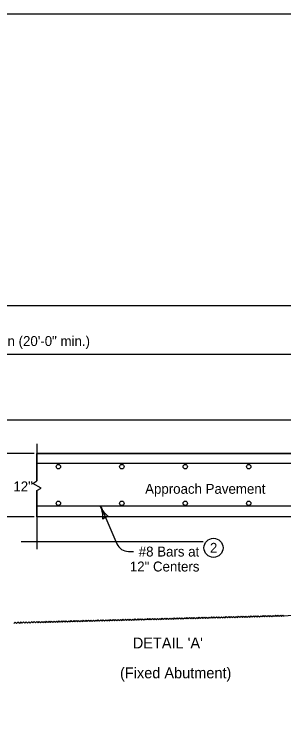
# Model space of a CAD drawing. Extents: x -2135039 to -2124495, y -2139046 to -2132546.
# Drawn here: x -2133798 to -2133364, y -2133685 to -2132546 of the extents above; entities that cross this region are included whole.
import ezdxf

# ---------------------------------------------------------------- set-up
doc = ezdxf.new("R2010")
doc.units = 0
for name, color, linetype in [('BridgeSuperStructureExisting', 7, 'Continuous'), ('dsnAlignmentStation', 7, 'Continuous'), ('dsnCellElements', 7, 'Continuous'), ('dsnStdLabel', 7, 'Continuous'), ('dsnStdLineWork', 7, 'Continuous')]:
    doc.layers.add(name, color=color, linetype=linetype)

msp = doc.modelspace()

# ---------------------------------------------------------------- linework, layer by layer
at = {"layer": 'BridgeSuperStructureExisting'}
for p, q in [((-2133761.6, -2133238.6), (-2133761.6, -2133298.7)), ((-2133142.6, -2133254.3), (-2133761.6, -2133254.3)), ((-2133761.6, -2133298.7), (-2133761.6, -2133254.3)), ((-2133761.6, -2133254.3), (-2133142.6, -2133254.3)), ((-2133157.7, -2133270.6), (-2133761.6, -2133270.6)), ((-2133761.6, -2133298.7), (-2133761.6, -2133298.7)), ((-2133761.6, -2133313.9), (-2133761.6, -2133408.5)), ((-2133761.6, -2133356.6), (-2133761.6, -2133313.9)), ((-2133157.7, -2133339.5), (-2133761.6, -2133339.5)), ((-2133142.6, -2133356.6), (-2133761.6, -2133356.6))]:
    msp.add_line(p, q, dxfattribs=at)
msp.add_lwpolyline([(-2133761.6, -2133313.9), (-2133755, -2133310.1), (-2133768.2, -2133302.5), (-2133761.6, -2133298.7)], dxfattribs=at)
msp.add_lwpolyline([(-2133761.6, -2133313.9), (-2133755, -2133310.1), (-2133768.2, -2133302.5), (-2133761.6, -2133298.7)], dxfattribs=at)
for centre, radius in [((-2133727.1, -2133275.6), 3.55), ((-2133624.8, -2133275.6), 3.55), ((-2133522.5, -2133275.6), 3.55), ((-2133420.2, -2133275.6), 3.55), ((-2133727.1, -2133334.6), 3.55), ((-2133624.8, -2133334.6), 3.55), ((-2133522.5, -2133334.6), 3.55), ((-2133420.2, -2133334.6), 3.55), ((-2133477, -2133406.4), 15.4)]:
    msp.add_circle(centre, radius, dxfattribs=at)
at = {"layer": 'dsnAlignmentStation'}
msp.add_lwpolyline([(-2134934.4, -2133016), (-2131799.4, -2133016), (-2131799.4, -2135026), (-2134934.4, -2135026)], close=True, dxfattribs=at)
at = {"layer": 'dsnCellElements'}
for centre, radius, start, end in [((-2133620, -2133322.8), 42.5, 203.6401, 231.7126), ((-2133697.9, -2133356.9), 42.5, 355.5676, 23.6401), ((-2133644.6, -2133372.5), 16.4, 95.9068, 131.3735)]:
    msp.add_arc(centre, radius, start, end, dxfattribs=at)
at = {"layer": 'dsnStdLabel'}
for p, q in [((-2134514.3, -2133094.1), (-2133142.6, -2133094.1)), ((-2133215.6, -2133200.6), (-2133828, -2133200.6)), ((-2133766.1, -2133254.4), (-2133865.6, -2133254.4)), ((-2133658.9, -2133339.8), (-2133632.6, -2133400)), ((-2133766.1, -2133356.7), (-2133865.6, -2133356.7)), ((-2133142.6, -2133356.6), (-2133761.6, -2133356.6)), ((-2133787.2, -2133396), (-2133493.8, -2133396)), ((-2133614.1, -2133412.1), (-2133605.9, -2133412.1)), ((-2133760.8, -2133526.1), (-2132665.9, -2133497.5))]:
    msp.add_line(p, q, dxfattribs=at)
for points in [[(-2133760.8, -2133526.1), (-2133759.8, -2133527.1), (-2133757.9, -2133525.1), (-2133755.9, -2133527), (-2133753.9, -2133525), (-2133751.9, -2133526.9), (-2133750, -2133524.9), (-2133747.9, -2133526.8), (-2133746, -2133524.8), (-2133743.9, -2133526.7), (-2133742, -2133524.7), (-2133740, -2133526.6), (-2133738.1, -2133524.5), (-2133736, -2133526.5), (-2133734.1, -2133524.4), (-2133732, -2133526.4), (-2133730.1, -2133524.3), (-2133728.1, -2133526.3), (-2133726.1, -2133524.2), (-2133724.1, -2133526.2), (-2133722.2, -2133524.1), (-2133720.2, -2133526.1), (-2133718.2, -2133524), (-2133716.2, -2133526), (-2133714.3, -2133523.9), (-2133713.2, -2133524.9)], [(-2133713.2, -2133524.9), (-2133712.2, -2133525.9), (-2133710.3, -2133523.8), (-2133708.2, -2133525.8), (-2133706.3, -2133523.7), (-2133704.3, -2133525.7), (-2133702.3, -2133523.6), (-2133700.3, -2133525.5), (-2133698.4, -2133523.5), (-2133696.3, -2133525.4), (-2133694.4, -2133523.4), (-2133692.4, -2133525.3), (-2133690.4, -2133523.3), (-2133688.4, -2133525.2), (-2133686.5, -2133523.2), (-2133684.4, -2133525.1), (-2133682.5, -2133523.1), (-2133680.5, -2133525), (-2133678.5, -2133523), (-2133676.5, -2133524.9), (-2133674.6, -2133522.9), (-2133672.5, -2133524.8), (-2133670.6, -2133522.8), (-2133668.6, -2133524.7), (-2133666.6, -2133522.7), (-2133665.6, -2133523.6)], [(-2133665.6, -2133523.6), (-2133664.6, -2133524.6), (-2133662.7, -2133522.6), (-2133660.6, -2133524.5), (-2133658.7, -2133522.5), (-2133656.7, -2133524.4), (-2133654.7, -2133522.4), (-2133652.7, -2133524.3), (-2133650.8, -2133522.3), (-2133648.7, -2133524.2), (-2133646.8, -2133522.2), (-2133644.8, -2133524.1), (-2133642.8, -2133522.1), (-2133640.8, -2133524), (-2133638.9, -2133522), (-2133636.8, -2133523.9), (-2133634.9, -2133521.9), (-2133632.9, -2133523.8), (-2133630.9, -2133521.8), (-2133628.9, -2133523.7), (-2133627, -2133521.7), (-2133624.9, -2133523.6), (-2133623, -2133521.5), (-2133621, -2133523.5), (-2133619, -2133521.4), (-2133618, -2133522.4)], [(-2133618, -2133522.4), (-2133617, -2133523.4), (-2133615.1, -2133521.3), (-2133613, -2133523.3), (-2133611.1, -2133521.2), (-2133609.1, -2133523.2), (-2133607.1, -2133521.1), (-2133605.1, -2133523.1), (-2133603.2, -2133521), (-2133601.1, -2133523), (-2133599.2, -2133520.9), (-2133597.2, -2133522.9), (-2133595.2, -2133520.8), (-2133593.2, -2133522.8), (-2133591.3, -2133520.7), (-2133589.2, -2133522.6), (-2133587.3, -2133520.6), (-2133585.3, -2133522.5), (-2133583.3, -2133520.5), (-2133581.3, -2133522.4), (-2133579.4, -2133520.4), (-2133577.3, -2133522.3), (-2133575.4, -2133520.3), (-2133573.4, -2133522.2), (-2133571.4, -2133520.2), (-2133570.4, -2133521.2)], [(-2133570.4, -2133521.2), (-2133569.4, -2133522.1), (-2133567.5, -2133520.1), (-2133565.4, -2133522), (-2133563.5, -2133520), (-2133561.5, -2133521.9), (-2133559.5, -2133519.9), (-2133557.5, -2133521.8), (-2133555.6, -2133519.8), (-2133553.5, -2133521.7), (-2133551.6, -2133519.7), (-2133549.6, -2133521.6), (-2133547.6, -2133519.6), (-2133545.6, -2133521.5), (-2133543.7, -2133519.5), (-2133541.6, -2133521.4), (-2133539.7, -2133519.4), (-2133537.6, -2133521.3), (-2133535.7, -2133519.3), (-2133533.7, -2133521.2), (-2133531.8, -2133519.2), (-2133529.7, -2133521.1), (-2133527.8, -2133519.1), (-2133525.7, -2133521), (-2133523.8, -2133519), (-2133522.8, -2133519.9)], [(-2133522.8, -2133519.9), (-2133521.8, -2133520.9), (-2133519.8, -2133518.9), (-2133517.8, -2133520.8), (-2133515.9, -2133518.7), (-2133513.8, -2133520.7), (-2133511.9, -2133518.6), (-2133509.9, -2133520.6), (-2133507.9, -2133518.5), (-2133505.9, -2133520.5), (-2133504, -2133518.4), (-2133501.9, -2133520.4), (-2133500, -2133518.3), (-2133498, -2133520.3), (-2133496, -2133518.2), (-2133494, -2133520.2), (-2133492.1, -2133518.1), (-2133490, -2133520.1), (-2133488.1, -2133518), (-2133486.1, -2133520), (-2133484.1, -2133517.9), (-2133482.1, -2133519.8), (-2133480.2, -2133517.8), (-2133478.1, -2133519.7), (-2133476.2, -2133517.7), (-2133475.2, -2133518.7)], [(-2133475.2, -2133518.7), (-2133474.2, -2133519.6), (-2133472.2, -2133517.6), (-2133470.2, -2133519.5), (-2133468.3, -2133517.5), (-2133466.2, -2133519.4), (-2133464.3, -2133517.4), (-2133462.3, -2133519.3), (-2133460.3, -2133517.3), (-2133458.3, -2133519.2), (-2133456.4, -2133517.2), (-2133454.3, -2133519.1), (-2133452.4, -2133517.1), (-2133450.4, -2133519), (-2133448.4, -2133517), (-2133446.4, -2133518.9), (-2133444.5, -2133516.9), (-2133442.4, -2133518.8), (-2133440.5, -2133516.8), (-2133438.5, -2133518.7), (-2133436.5, -2133516.7), (-2133434.5, -2133518.6), (-2133432.6, -2133516.6), (-2133430.5, -2133518.5), (-2133428.6, -2133516.5), (-2133427.6, -2133517.4)], [(-2133427.6, -2133517.4), (-2133426.6, -2133518.4), (-2133424.6, -2133516.4), (-2133422.6, -2133518.3), (-2133420.7, -2133516.3), (-2133418.6, -2133518.2), (-2133416.7, -2133516.2), (-2133414.7, -2133518.1), (-2133412.7, -2133516.1), (-2133410.7, -2133518), (-2133408.8, -2133515.9), (-2133406.7, -2133517.9), (-2133404.8, -2133515.8), (-2133402.8, -2133517.8), (-2133400.8, -2133515.7), (-2133398.8, -2133517.7), (-2133396.9, -2133515.6), (-2133394.8, -2133517.6), (-2133392.9, -2133515.5), (-2133390.9, -2133517.5), (-2133388.9, -2133515.4), (-2133386.9, -2133517.4), (-2133385, -2133515.3), (-2133382.9, -2133517.3), (-2133381, -2133515.2), (-2133380, -2133516.2)], [(-2133380, -2133516.2), (-2133379, -2133517.2), (-2133377, -2133515.1), (-2133375, -2133517.1), (-2133373.1, -2133515), (-2133371, -2133516.9), (-2133369.1, -2133514.9), (-2133367.1, -2133516.8), (-2133365.1, -2133514.8), (-2133363.1, -2133516.7)], [(-2133760.6, -2133526.3), (-2133761.7, -2133525.2), (-2133763.9, -2133527.4), (-2133766.1, -2133525.3), (-2133768.2, -2133527.5), (-2133770.4, -2133525.4), (-2133772.6, -2133527.7), (-2133774.8, -2133525.5), (-2133776.9, -2133527.8), (-2133779.2, -2133525.7), (-2133781.3, -2133527.9), (-2133783.5, -2133525.8), (-2133785.6, -2133528), (-2133787.9, -2133525.9), (-2133790, -2133528.1), (-2133792.2, -2133526), (-2133794.4, -2133528.2), (-2133796.6, -2133526.1), (-2133798.7, -2133528.3)]]:
    msp.add_lwpolyline(points, dxfattribs=at)
msp.add_arc((-2133614.1, -2133391.9), 20.2, 203.6401, 270, dxfattribs=at)
at = {"layer": 'dsnStdLineWork'}
msp.add_lwpolyline([(-2135038.9, -2135130.5), (-2131694.9, -2135130.5), (-2131694.9, -2132546.5), (-2135038.9, -2132546.5)], close=True, dxfattribs=at)

# ---------------------------------------------------------------- texts
at = {"layer": 'BridgeSuperStructureExisting'}
msp.add_text("DETAIL 'A' ", height=17.5, dxfattribs=at).set_placement((-2133607.1, -2133568.4))
at = {"layer": 'dsnStdLabel'}
for s, height, p in [('Double Reinforced Section (20\'-0" min.)', 16, (-2134051.7, -2133081.2)), ('12"', 16, (-2133799.6, -2133315.4)), ('Approach Pavement', 16, (-2133587.2, -2133319.3)), ('2', 16, (-2133482.7, -2133414.4)), ('#8 Bars at', 16, (-2133597.5, -2133420.4)), ('12" Centers', 16, (-2133611.9, -2133444.5)), ('(Fixed Abutment)', 17.5, (-2133627.7, -2133616.6))]:
    msp.add_text(s, height=height, dxfattribs=at).set_placement(p)

doc.saveas('drawing.dxf')
